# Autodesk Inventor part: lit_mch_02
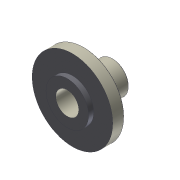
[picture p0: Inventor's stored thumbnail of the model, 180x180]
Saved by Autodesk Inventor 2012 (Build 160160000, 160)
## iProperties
Created: 2002-07
Part Number: lit_mch_02
Document SubType Name: Modeling
Designer: Lieven Grauls
Stock Number: lit_mch_02
Project: Valve Techcamp 2008
Density: 1 g/cm^3
Mass: 297.985 g
Surface Area: 511.854 cm^2
Volume: 297.985 cm^3
Material: Default
Company: Autodesk
Control State: 0
Master: False
Checked Out: False
Shininess: 64.0
Length Units: 11269
Angle Units: 11279
Time Units: 11290
Mass Units: 11283
Length Display Precision: 3
Angle Display Precision: 2
Density: 0.0
Volumn: 0.0
Area: 0.0
PropertySet Name: Model Information
Author: Lieven Grauls
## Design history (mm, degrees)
node "lit_cast_02" dims "d1" = 10
sketch "Sketch2"
  geometry: L1 (0, 35.8)-(0, -11.8) reference; L2 (0, 1)-(37, 1); L3 (20, 1)-(-20, 1) reference; L4 (37, 1)-(37, 10); L5 (37, 10)-(75, 10); L6 (75, 10)-(75, -5); L7 (75, -5)-(0, -5); L8 (70, 29)-(70, 10) reference; L9 (69, 9)-(-69, 9) reference; L10 (37, 0)-(-37, 0) reference; 1 further point
  constraints: 10 end point, 2 parallel, 2 perpendicular, 2 point on line, 1 collinear
  dimensions: "d2" = 1 distance between parallel lines of L10 L2; "d3" = 1 distance between parallel lines of L9 L5; "d4" = 5 distance between parallel lines of L6 L8; "d5" = 5 distance between parallel lines of L7 L10; "d6" = 74 diameter of L4 L1
revolve "Revolution1" sketch "Sketch2" stored, may be unused: angle "d7" = 90 deg
sketch "Sketch8"
  geometry: C1 r 6.335 at (0, 0); C2 r 27 at (0, 0) reference; 1 further point
  constraints: 1 centre point, 1 coincident
  dimensions: "d63" = 12.67 diameter of C1
extrude "Extrusion2" join sketch "Sketch8" stored distance "d61" = 10; taper "d62" = 0 deg
node "Volumenkörper1"
node "Volumenkörpern"
node "Oberflächenkörpern"
tag "Bezeichnung2"
feature "Volumenkörper1::lit_cast_02" dims "d1" = 10
